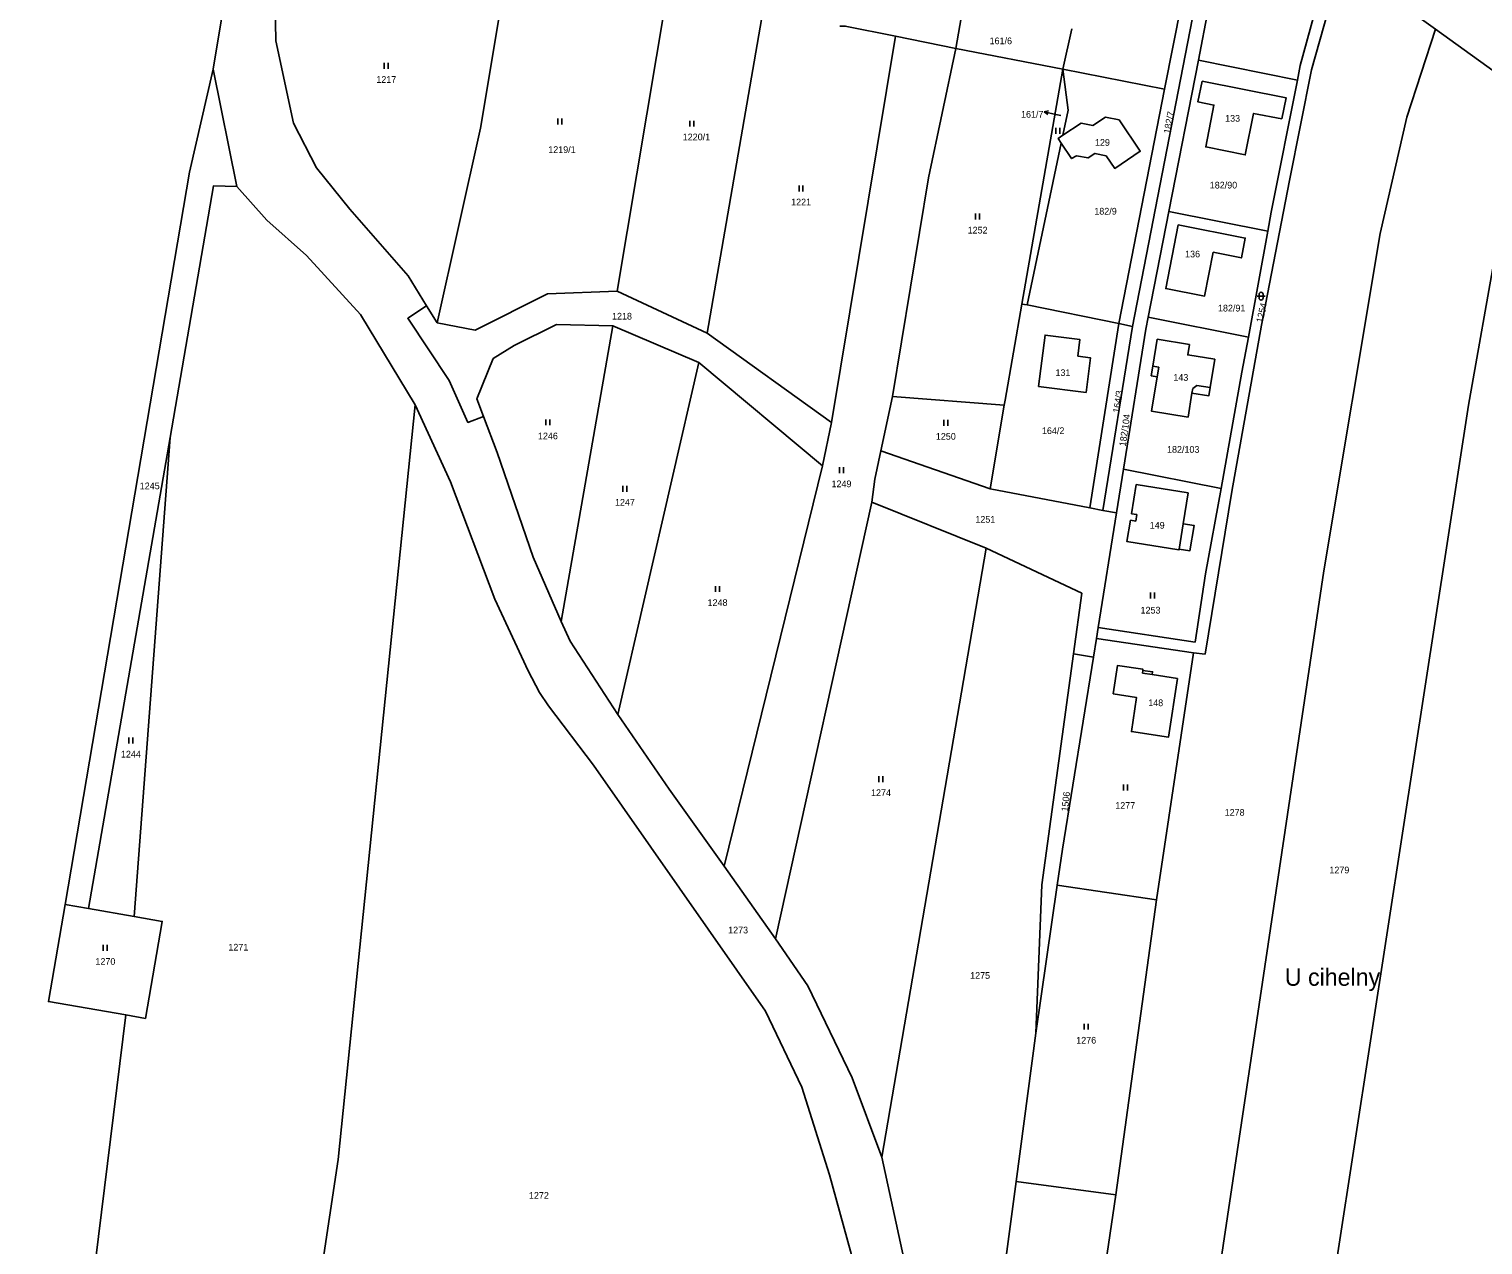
# Model space of a CAD drawing. Extents: x -746176 to -739709, y -1128407 to -1124482.
# Drawn here: x -742234.3 to -741865.4, y -1126742 to -1126433.2 of the extents above; entities that cross this region are included whole.
import ezdxf

# ---------------------------------------------------------------- set-up
doc = ezdxf.new("R2010")
doc.units = 0
for name, color, linetype in [('Vrstva 33', 7, 'Continuous'), ('Vrstva 42', 7, 'Continuous'), ('Vrstva 43', 7, 'Continuous'), ('Vrstva 44', 7, 'Continuous'), ('Vrstva 47', 7, 'Continuous')]:
    doc.layers.add(name, color=color, linetype=linetype)

msp = doc.modelspace()

# ---------------------------------------------------------------- linework, layer by layer
at = {"layer": 'Vrstva 33'}
for p, q in [((-741999.11, -1126438.17), (-741996.32, -1126421.94)), ((-742072.53, -1126424.54), (-742085.13, -1126499.75)), ((-742048.06, -1126428.34), (-742062.27, -1126510.43)), ((-741971.96, -1126443.41), (-741969.67, -1126433.17)), ((-741854.95, -1126449.53), (-741877.38, -1126433.3)), ((-742030.73, -1126533.18), (-742014.43, -1126435)), ((-742014.43, -1126435), (-741999.11, -1126438.17)), ((-741999.11, -1126438.17), (-741971.96, -1126443.41)), ((-742181.63, -1126473.18), (-742187.6, -1126443.43)), ((-741971.96, -1126443.41), (-741982.39, -1126503.11)), ((-741971.96, -1126443.41), (-741946.15, -1126448.52)), ((-741937.58, -1126441.15), (-741945.07, -1126479.55)), ((-741937.58, -1126441.15), (-741912.45, -1126446.2)), ((-741946.15, -1126448.52), (-741957.75, -1126508.02)), ((-741981.04, -1126503.23), (-741972.39, -1126462.23)), ((-741945.07, -1126479.55), (-741950.3, -1126506.42)), ((-741945.07, -1126479.55), (-741919.95, -1126484.52)), ((-741924.9, -1126511.47), (-741919.95, -1126484.52)), ((-742062.27, -1126510.43), (-742085.13, -1126499.75)), ((-742130.78, -1126507.86), (-742133.47, -1126503.52)), ((-741982.39, -1126503.11), (-741981.04, -1126503.23)), ((-741981.04, -1126503.23), (-741957.75, -1126508.02)), ((-741950.3, -1126506.42), (-741924.9, -1126511.47)), ((-742099.34, -1126583.64), (-742086.2, -1126508.61)), ((-742086.2, -1126508.61), (-742064.37, -1126517.89)), ((-742030.73, -1126533.18), (-742062.27, -1126510.43)), ((-741965.17, -1126554.82), (-741957.75, -1126508.02)), ((-741961.8, -1126555.46), (-741954.32, -1126508.73)), ((-741957.75, -1126508.02), (-741954.32, -1126508.73)), ((-742084.93, -1126607.27), (-742064.37, -1126517.89)), ((-742064.37, -1126517.89), (-742032.96, -1126544.11)), ((-742015.23, -1126526.56), (-742018.18, -1126540.36)), ((-741986.84, -1126528.78), (-742015.23, -1126526.56)), ((-741986.84, -1126528.78), (-741990.4, -1126550.02)), ((-742032.96, -1126544.11), (-742030.73, -1126533.18)), ((-742219.28, -1126656.58), (-742198.58, -1126536.93)), ((-742198.58, -1126536.93), (-742207.72, -1126658.58)), ((-742018.18, -1126540.36), (-741990.4, -1126550.02)), ((-742057.95, -1126645.76), (-742032.96, -1126544.11)), ((-741958.35, -1126556.11), (-741956.57, -1126544.99)), ((-741956.57, -1126544.99), (-741931.8, -1126549.92)), ((-741990.4, -1126550.02), (-741965.17, -1126554.82)), ((-742020.49, -1126553.4), (-742044.92, -1126664.26)), ((-741991.43, -1126565.04), (-742020.49, -1126553.4)), ((-741965.17, -1126554.82), (-741961.8, -1126555.46)), ((-741961.8, -1126555.46), (-741958.35, -1126556.11)), ((-741958.35, -1126556.11), (-741963.01, -1126585.21)), ((-742017.91, -1126719.67), (-741991.43, -1126565.04)), ((-741963.45, -1126587.97), (-741964.22, -1126592.75)), ((-741963.01, -1126585.21), (-741963.45, -1126587.97)), ((-741963.45, -1126587.97), (-741938.82, -1126591.67)), ((-741964.22, -1126592.75), (-741969.26, -1126591.89)), ((-741938.82, -1126591.67), (-741948.24, -1126654.37)), ((-742044.92, -1126664.26), (-742057.95, -1126645.76)), ((-741973.39, -1126650.59), (-741978.81, -1126688.21)), ((-741948.24, -1126654.37), (-741973.39, -1126650.59)), ((-741958.56, -1126729.22), (-741948.24, -1126654.37)), ((-742225.19, -1126655.56), (-742219.28, -1126656.58)), ((-742207.72, -1126658.58), (-742219.28, -1126656.58)), ((-741978.81, -1126688.21), (-741983.83, -1126725.85)), ((-741983.83, -1126725.85), (-741958.56, -1126729.22))]:
    msp.add_line(p, q, dxfattribs=at)
for points in [[(-742187.6, -1126443.43), (-742182.48, -1126412.17), (-742177.55, -1126374.98), (-742174.74, -1126350.1), (-742174.68, -1126346.91)], [(-742133.47, -1126503.52), (-742138.17, -1126495.9), (-742152.98, -1126479.01), (-742161.38, -1126468.51), (-742167.25, -1126457.12), (-742171.72, -1126436.22), (-742172.13, -1126413.04), (-742170.12, -1126398.06)], [(-741954.32, -1126508.73), (-741938.56, -1126427.78), (-741932.77, -1126409.29)], [(-741936.11, -1126408.24), (-741941.9, -1126426.74), (-741946.15, -1126448.52)], [(-741925.07, -1126408.25), (-741929.41, -1126410.36), (-741935.06, -1126428.26), (-741937.58, -1126441.15)], [(-742130.78, -1126507.86), (-742119.81, -1126458.38), (-742113.18, -1126418.78)], [(-741912.45, -1126446.2), (-741911.72, -1126442.48), (-741904.57, -1126416.23)], [(-741898.42, -1126419.6), (-741902.57, -1126421.34), (-741908.84, -1126443.59), (-741914.46, -1126471.66), (-741921.58, -1126508.41), (-741929.05, -1126550.68), (-741935.86, -1126591.95), (-741938.82, -1126591.67)], [(-741877.38, -1126433.3), (-741887.7, -1126425.84), (-741898.42, -1126419.6)], [(-742028.56, -1126432.53), (-742027.22, -1126432.46), (-742014.43, -1126435)], [(-741949.18, -1126838.52), (-741941.96, -1126813.45), (-741924.2, -1126694.57), (-741905.72, -1126570.83), (-741891.45, -1126485.12), (-741884.64, -1126455.59), (-741877.38, -1126433.3)], [(-741999.11, -1126438.17), (-742006.04, -1126471.03), (-742015.23, -1126526.56)], [(-742187.6, -1126443.43), (-742193.63, -1126469.56), (-742225.19, -1126655.56)], [(-741971.96, -1126460.21), (-741970.61, -1126453.82), (-741971.96, -1126443.41)], [(-741916.39, -1126456.06), (-741923.58, -1126454.64), (-741925.69, -1126465.18), (-741935.73, -1126463.15), (-741933.62, -1126452.56), (-741937.69, -1126451.75), (-741936.62, -1126446.48), (-741915.3, -1126450.71), (-741916.39, -1126456.06)], [(-741919.95, -1126484.52), (-741919.07, -1126479.73), (-741912.45, -1126446.2)], [(-741854.95, -1126449.53), (-741869, -1126528.7), (-741885.6, -1126636.32), (-741902.19, -1126743.95), (-741911.69, -1126803.9), (-741921.19, -1126863.86)], [(-741971.96, -1126460.21), (-741967.36, -1126457.11), (-741964.34, -1126457.73), (-741961.18, -1126455.63), (-741957.72, -1126456.31), (-741952.34, -1126464.28), (-741958.81, -1126468.63), (-741961.01, -1126465.4), (-741963.86, -1126464.82), (-741965.59, -1126465.96), (-741968.54, -1126465.39), (-741969.75, -1126466.13), (-741972.39, -1126462.23)], [(-741972.39, -1126462.23), (-741973.19, -1126461.04), (-741971.96, -1126460.21)], [(-742198.58, -1126536.93), (-742187.57, -1126473.06), (-742181.63, -1126473.18)], [(-742136.32, -1126528.63), (-742150.26, -1126505.72), (-742163.9, -1126490.76), (-742174, -1126481.74), (-742181.63, -1126473.18)], [(-741933.81, -1126489.89), (-741936.01, -1126501.05), (-741945.87, -1126499.14), (-741942.7, -1126482.95), (-741925.67, -1126486.3), (-741926.64, -1126491.33), (-741933.81, -1126489.89)], [(-742085.13, -1126499.75), (-742102.79, -1126500.44), (-742121.1, -1126509.69), (-742130.78, -1126507.86)], [(-742133.47, -1126503.52), (-742138.24, -1126506.67), (-742127.69, -1126522.49), (-742122.99, -1126533.1), (-742119.02, -1126531.6)], [(-741982.39, -1126503.11), (-741986.61, -1126527.43), (-741986.84, -1126528.78)], [(-741950.3, -1126506.42), (-741950.88, -1126509.4), (-741956.57, -1126544.99)], [(-742119.02, -1126531.6), (-742120.68, -1126527.1), (-742116.58, -1126516.91), (-742111.25, -1126513.62), (-742100.5, -1126508.24), (-742086.2, -1126508.61)], [(-741966.09, -1126525.52), (-741978.13, -1126523.98), (-741976.5, -1126510.95), (-741967.68, -1126512.06), (-741968.17, -1126516.26), (-741964.97, -1126516.71), (-741966.09, -1126525.52)], [(-741949.54, -1126521.3), (-741949.14, -1126518.84), (-741948.01, -1126512), (-741939.86, -1126513.36), (-741940.29, -1126515.97), (-741933.44, -1126517.1), (-741934.6, -1126524.26), (-741934.95, -1126526.39), (-741939.23, -1126525.71), (-741940.21, -1126531.75), (-741949.49, -1126530.23), (-741948.05, -1126521.55), (-741949.54, -1126521.3)], [(-741931.8, -1126549.92), (-741926.53, -1126520.32), (-741924.9, -1126511.47)], [(-742178.83, -1126851.05), (-742171.32, -1126822.78), (-742155.89, -1126720.33), (-742136.32, -1126528.63)], [(-741999.58, -1126809.75), (-742010.53, -1126795.36), (-742015.95, -1126779.71), (-742017.83, -1126773.98), (-742019.18, -1126767.51), (-742024.98, -1126746.93), (-742031.2, -1126724.22), (-742038.23, -1126701.93), (-742047.45, -1126682.61), (-742091.11, -1126620.17), (-742102.48, -1126605.07), (-742104.79, -1126601.7), (-742107.64, -1126596.22), (-742116.14, -1126577.99), (-742127.39, -1126548.21), (-742136.32, -1126528.63)], [(-742099.34, -1126583.64), (-742106.44, -1126567.33), (-742115.57, -1126540.78), (-742119.02, -1126531.6)], [(-742018.18, -1126540.36), (-742019.72, -1126547.57), (-742020.49, -1126553.4)], [(-741963.01, -1126585.21), (-741938.41, -1126588.9), (-741935.8, -1126571.55), (-741931.8, -1126549.92)], [(-741942.48, -1126565.27), (-741942.51, -1126565.48), (-741955.71, -1126563.36), (-741954.79, -1126557.96), (-741953.49, -1126558.18), (-741953.24, -1126556.54), (-741954.54, -1126556.33), (-741953.34, -1126548.91), (-741940.2, -1126551.04), (-741941.46, -1126558.9), (-741938.67, -1126559.28), (-741939.72, -1126565.72), (-741942.48, -1126565.27)], [(-741969.26, -1126591.89), (-741967.19, -1126576.48), (-741991.43, -1126565.04)], [(-742084.93, -1126607.27), (-742096.98, -1126588.69), (-742099.34, -1126583.64)], [(-741978.81, -1126688.21), (-741977.33, -1126650.54), (-741969.26, -1126591.89)], [(-741964.22, -1126592.75), (-741972.08, -1126641.48), (-741973.39, -1126650.59)], [(-741959.21, -1126602.06), (-741958.13, -1126594.85), (-741951.65, -1126595.81), (-741951.69, -1126596.09), (-741949.2, -1126596.45), (-741949.3, -1126597.17), (-741942.9, -1126598.15), (-741945.13, -1126613.03), (-741954.59, -1126611.62), (-741953.3, -1126602.96), (-741959.21, -1126602.06)], [(-742057.95, -1126645.76), (-742071.88, -1126626.21), (-742084.93, -1126607.27)], [(-742225.19, -1126655.56), (-742229.45, -1126680.19), (-742209.78, -1126683.59)], [(-742209.78, -1126683.59), (-742204.82, -1126684.45), (-742200.55, -1126659.82), (-742207.72, -1126658.58)], [(-742044.92, -1126664.26), (-742036.67, -1126676.18), (-742025.42, -1126699.58), (-742017.91, -1126719.67)], [(-742209.78, -1126683.59), (-742220.66, -1126771.42), (-742228.09, -1126808.59), (-742234.35, -1126828.88)], [(-742017.91, -1126719.67), (-742012.75, -1126743.47), (-742007.6, -1126764.33), (-742004.26, -1126772.24), (-741997.55, -1126789.67), (-741994.96, -1126793.61)], [(-741994.96, -1126793.61), (-741988.23, -1126758.85), (-741983.83, -1126725.85)], [(-741958.56, -1126729.22), (-741962.62, -1126756.79), (-741970.12, -1126797.93), (-741975.77, -1126814.25)]]:
    msp.add_lwpolyline(points, dxfattribs=at)
at = {"layer": 'Vrstva 43'}
for p, q in [((-741976.69, -1126454.23), (-741975.61, -1126453.96)), ((-741973.77, -1126454.9), (-741976.69, -1126454.23)), ((-741976.69, -1126454.23), (-741975.83, -1126454.94)), ((-741972.47, -1126455.21), (-741973.77, -1126454.9))]:
    msp.add_line(p, q, dxfattribs=at)
at = {"layer": 'Vrstva 44'}
for p, q in [((-742144.22, -1126443.34), (-742144.22, -1126441.84)), ((-742143.22, -1126443.34), (-742143.22, -1126441.84)), ((-742100.15, -1126457.48), (-742100.15, -1126455.98)), ((-742099.15, -1126457.48), (-742099.15, -1126455.98)), ((-742066.66, -1126458), (-742066.66, -1126456.5)), ((-742065.66, -1126458), (-742065.66, -1126456.5)), ((-741973.78, -1126459.82), (-741973.78, -1126458.32)), ((-741972.78, -1126459.82), (-741972.78, -1126458.32)), ((-742038.94, -1126474.45), (-742038.94, -1126472.95)), ((-742037.94, -1126474.45), (-742037.94, -1126472.95)), ((-741994.14, -1126481.6), (-741994.14, -1126480.1)), ((-741993.14, -1126481.6), (-741993.14, -1126480.1)), ((-741922.67, -1126501.05), (-741920.67, -1126501.05)), ((-741922.17, -1126500.55), (-741922.17, -1126501.55)), ((-741921.17, -1126501.55), (-741921.17, -1126500.55)), ((-742103.2, -1126533.86), (-742103.2, -1126532.36)), ((-742102.2, -1126533.86), (-742102.2, -1126532.36)), ((-742002.21, -1126533.97), (-742002.21, -1126532.47)), ((-742001.21, -1126533.97), (-742001.21, -1126532.47)), ((-742028.69, -1126546.02), (-742028.69, -1126544.52)), ((-742027.69, -1126546.02), (-742027.69, -1126544.52)), ((-742083.65, -1126550.71), (-742083.65, -1126549.21)), ((-742082.65, -1126550.71), (-742082.65, -1126549.21)), ((-742060.15, -1126576.18), (-742060.15, -1126574.68)), ((-742059.15, -1126576.18), (-742059.15, -1126574.68)), ((-741949.74, -1126577.8), (-741949.74, -1126576.3)), ((-741948.74, -1126577.8), (-741948.74, -1126576.3)), ((-742209.04, -1126614.66), (-742209.04, -1126613.16)), ((-742208.04, -1126614.66), (-742208.04, -1126613.16)), ((-742018.66, -1126624.45), (-742018.66, -1126622.95)), ((-742017.66, -1126624.45), (-742017.66, -1126622.95)), ((-741956.57, -1126626.59), (-741956.57, -1126625.09)), ((-741955.57, -1126626.59), (-741955.57, -1126625.09)), ((-742215.51, -1126667.3), (-742215.51, -1126665.8)), ((-742214.51, -1126667.3), (-742214.51, -1126665.8)), ((-741966.58, -1126687.31), (-741966.58, -1126685.81)), ((-741965.58, -1126687.31), (-741965.58, -1126685.81))]:
    msp.add_line(p, q, dxfattribs=at)
for centre, start, end in [((-741921.67, -1126500.55), 0, 180), ((-741921.67, -1126501.55), 180, 359.9879)]:
    msp.add_arc(centre, 0.5, start, end, dxfattribs=at)
at = {"layer": 'Vrstva 47'}
for p, q in [((-741949.14, -1126518.84), (-741947.64, -1126519.08)), ((-741947.64, -1126519.08), (-741948.05, -1126521.55)), ((-741939.03, -1126524.51), (-741939.23, -1126525.71)), ((-741937.97, -1126523.73), (-741939.03, -1126524.51)), ((-741934.6, -1126524.26), (-741937.97, -1126523.73)), ((-741942.48, -1126565.27), (-741941.46, -1126558.9)), ((-741951.69, -1126596.09), (-741951.8, -1126596.82)), ((-741951.8, -1126596.82), (-741949.3, -1126597.17))]:
    msp.add_line(p, q, dxfattribs=at)

# ---------------------------------------------------------------- texts
at = {"layer": 'Vrstva 42'}
for s, p in [('161/6', (-741990.57, -1126437.08)), ('1217', (-742146.22, -1126446.89)), ('161/7', (-741982.6, -1126455.73)), ('133', (-741930.79, -1126456.75)), ('1219/1', (-742102.58, -1126464.69)), ('1220/1', (-742068.45, -1126461.49)), ('129', (-741963.83, -1126462.88)), ('182/90', (-741934.69, -1126473.72)), ('1221', (-742040.94, -1126478)), ('182/9', (-741963.99, -1126480.34)), ('1252', (-741996.14, -1126485.15)), ('136', (-741940.95, -1126491.22)), ('182/91', (-741932.61, -1126504.95)), ('1218', (-742086.4, -1126507)), ('131', (-741973.85, -1126521.34)), ('143', (-741943.93, -1126522.55)), ('1246', (-742105.2, -1126537.41)), ('1250', (-742004.21, -1126537.52)), ('164/2', (-741977.28, -1126536.08)), ('182/103', (-741945.54, -1126540.83)), ('1249', (-742030.69, -1126549.57)), ('1245', (-742206.26, -1126550.09)), ('1247', (-742085.65, -1126554.26)), ('1251', (-741994.19, -1126558.59)), ('149', (-741949.93, -1126560.09)), ('1248', (-742062.15, -1126579.73)), ('1253', (-741952.26, -1126581.65)), ('148', (-741950.3, -1126605.17)), ('1244', (-742211.04, -1126618.21)), ('1274', (-742020.66, -1126628)), ('1277', (-741958.68, -1126631.24)), ('1278', (-741930.91, -1126633)), ('1279', (-741904.33, -1126647.63)), ('1273', (-742056.93, -1126662.88)), ('1271', (-742183.77, -1126667.23)), ('1270', (-742217.51, -1126670.85)), ('1275', (-741995.51, -1126674.41)), ('1276', (-741968.58, -1126690.86)), ('1272', (-742107.49, -1126730.27))]:
    msp.add_text(s, height=1.7, dxfattribs=at).set_placement(p)
for s, rotation, p in [('182/7', 79, (-741944.77, -1126459.91)), ('1254', 77, (-741921.27, -1126507.92)), ('164/3', 81, (-741957.64, -1126530.79)), ('182/104', 82, (-741956.01, -1126539.29)), ('1506', 84, (-741970.68, -1126632))]:
    msp.add_text(s, height=1.7, rotation=rotation, dxfattribs=at).set_placement(p)
at = {"layer": 'Vrstva 43'}
msp.add_text('U cihelny', height=4.4, dxfattribs=at).set_placement((-741915.64, -1126676.18))

doc.saveas('drawing.dxf')
